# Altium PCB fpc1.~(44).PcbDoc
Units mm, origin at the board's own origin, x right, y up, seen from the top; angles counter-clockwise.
Board outline 89.5 x 7.33 mm, 2 copper layers (Top Layer, Bottom Layer), stack 0.049 mm thick; 5 components, 5 nets, 20 pads, 5 vias.
Unrouted connection lines stored in the file: 8.
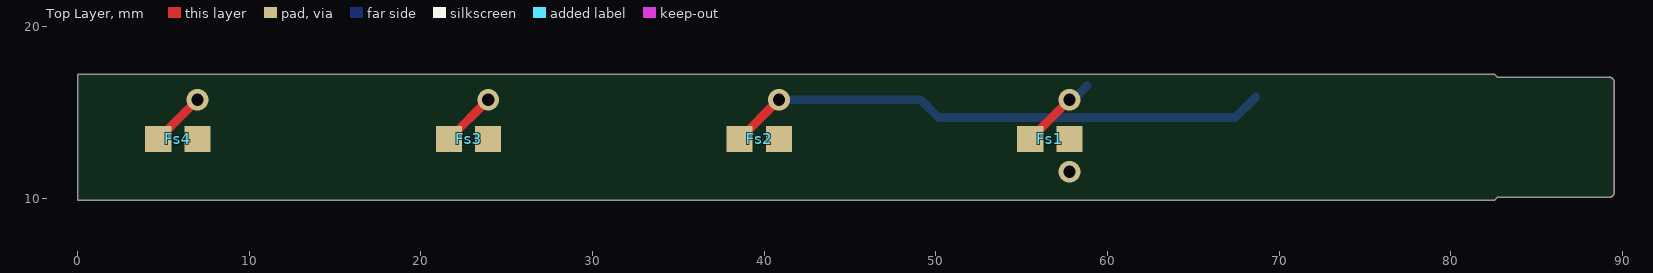
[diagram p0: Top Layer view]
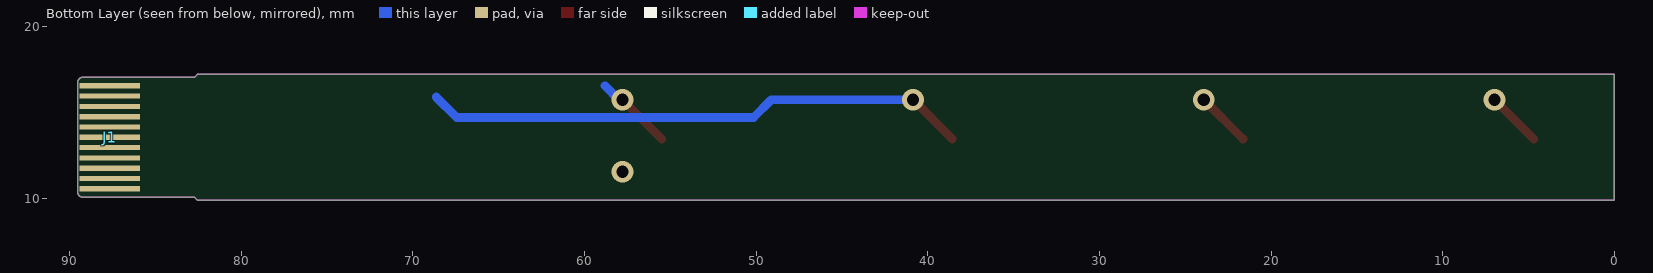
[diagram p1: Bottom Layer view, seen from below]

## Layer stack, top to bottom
Top Solder: solder mask 0.0102, Solder Resist, Dk 3.5
Top Layer: signal copper 0.012
Dielectric 1: dielectric 0.025, FR-4, Dk 4.8
Bottom Layer: signal copper 0.012
Bottom Solder: solder mask 0.0102, Solder Resist, Dk 3.5

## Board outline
0.013,9.893 0.013,17.225 82.547,17.225 82.713,17.059 89.213,17.059 cw(c89.213,16.759) 89.513,16.759 89.513,10.359 cw(c89.213,10.359) 89.213,10.059 82.713,10.059 82.547,9.893

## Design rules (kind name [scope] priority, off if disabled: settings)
BoardOutlineClearance [All] p1: gap=0 ignorepadtopadclearanceinfootprint=FALSE except(0.254: Via-OutlineEdge Via-CavityEdge Via-CutoutEdge Via-SplitBarrior Fill-OutlineEdge Fill-CavityEdge Fill-CutoutEdge Fill-SplitBarrior Poly-OutlineEdge Poly-CavityEdge Poly-CutoutEdge Poly-SplitBarrior Region-OutlineEdge Region-CavityEdge Region-CutoutEdge Region-SplitBarrior Text-OutlineEdge Text-CavityEdge Text-CutoutEdge Text-SplitBarrior)
Clearance [All] p1: gap=0.076 ignorepadtopadclearanceinfootprint=TRUE except(0: Arc-Hole Track-Hole SMDPad-Hole THPad-Hole Via-Hole Fill-Hole Poly-Hole Region-Hole Text-Hole)
DiffPairsRouting [All] p1: maxlimit=0.254 minlimit=0.254 mostfreqgap=0.254 toplayer_minwidth=0.381 toplayer_maxwidth=0.381 toplayer_prefwidth=0.381 bottomlayer_minwidth=0.381 bottomlayer_maxwidth=0.381 bottomlayer_prefwidth=0.381 substack1={6BAC4FC8-8DE6-4E41-AF8A-9441F3E19743} toplayer_{6bac4fc8-8de6-4e41-af8a-9441f3e19743}_minwidth=0.381 toplayer_{6bac4fc8-8de6-4e41-af8a-9441f3e19743}_maxwidth=0.381 toplayer_{6bac4fc8-8de6-4e41-af8a-9441f3e19743}_prefwidth=0.381 bottomlayer_{6bac4fc8-8de6-4e41-af8a-9441f3e19743}_minwidth=0.381 bottomlayer_{6bac4fc8-8de6-4e41-af8a-9441f3e19743}_maxwidth=0.381 bottomlayer_{6bac4fc8-8de6-4e41-af8a-9441f3e19743}_prefwidth=0.381 maxuncoupledlength=12.7
MinimumSolderMaskSliver [All] p1: minsoldermaskwidth=0.05
PolygonConnect [All] p1: connectstyle=Relief reliefconductorwidth=0.254 reliefentries=4 polygonreliefangle="90 Angle" airgapwidth=0.254
RoutingVias [All] p1: holewidth=0.711 width=1.27 viastyle="Through Hole" minholewidth=0.711 minwidth=1.27 maxholewidth=0.711 maxwidth=1.27
SilkToSilkClearance [All] p1: silktosilkclearance=0.05
SilkToSolderMaskClearance [IsPad] p1: minsilkscreentomaskgap=0.05 clearancetoexposedcopper=TRUE
SolderMaskExpansion [All] p1: expansion=0.102 istentingtop=FALSE
Width [All] p1: maxlimit=0.508 minlimit=0.254 preferedwidth=0.381 substack1={6BAC4FC8-8DE6-4E41-AF8A-9441F3E19743} toplayer_{6bac4fc8-8de6-4e41-af8a-9441f3e19743}_maxwidth=0.254 toplayer_{6bac4fc8-8de6-4e41-af8a-9441f3e19743}_prefwidth=0.254 bottomlayer_{6bac4fc8-8de6-4e41-af8a-9441f3e19743}_maxwidth=0.254 bottomlayer_{6bac4fc8-8de6-4e41-af8a-9441f3e19743}_prefwidth=0.254 minimp=50.000000 maximp=50.000000 favimp=50.000000
26 further rules are at their usual default settings.

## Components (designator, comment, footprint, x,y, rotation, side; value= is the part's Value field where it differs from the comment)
Fs1 "ForceSensor" sensor_connector 56.642,13.462 r0 top
Fs2 "ForceSensor" sensor_connector 39.709,13.462 r0 top
Fs3 "ForceSensor" sensor_connector 22.775,13.462 r0 top
Fs4 "ForceSensor" sensor_connector 5.842,13.462 r0 top
J1 "FPC_connector" FPC_connector 87.65,13.559 r180 bottom

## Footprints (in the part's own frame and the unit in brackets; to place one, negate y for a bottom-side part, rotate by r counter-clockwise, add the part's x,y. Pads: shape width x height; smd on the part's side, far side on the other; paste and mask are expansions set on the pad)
FPC_connector [mm]
  rect 3.5x0.3 smd: 0(0,3) 1(0,3) 2(0,2.4) 3(0,1.8) 4(0,1.2) 5(0,0.6) 6(0,0) 7(0,-0.6) 8(0,-1.2) 9(0,-1.8) 10(0,-2.4) 11(0,-3)
sensor_connector [mil]
  rect 60x60 smd: 0(-45,0) 1(45,0)

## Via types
v1: diameter 1.27, hole 0.711, Top Layer to Bottom Layer, 5 vias

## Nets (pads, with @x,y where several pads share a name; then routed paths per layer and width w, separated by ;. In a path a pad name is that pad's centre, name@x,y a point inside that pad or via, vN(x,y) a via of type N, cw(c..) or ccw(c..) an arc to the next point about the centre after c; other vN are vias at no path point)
FS1: Fs1.0 J1.1 | length 4.6
  Top Layer w0.508: Fs1.0 v1(57.785,15.748)
  Bottom Layer w0.508: v1(57.785,15.748) 57.991,15.748 58.802,16.559
FS2: Fs2.0 J1.2 | length 31.9
  Top Layer w0.508: Fs2.0 v1(40.852,15.748)
  Bottom Layer w0.508: v1(40.852,15.748) 49.117,15.748 50.156,14.709 67.433,14.709 68.625,15.901
FS3: Fs3.0 J1.3 | length 3.2
  Top Layer w0.508: Fs3.0 v1(23.918,15.748)
FS4: Fs4.0 J1.4 | length 3.2
  Top Layer w0.508: Fs4.0 v1(6.985,15.748)
GND: Fs1.1 Fs2.1 Fs3.1 Fs4.1 J1.0
pads on no net: J1.5 J1.6 J1.7 J1.8 J1.9 J1.10 J1.11
copper on no net:
  other v1: 57.785,11.557

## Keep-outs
Keep-Out Layer:
  the board outline again, w0.013

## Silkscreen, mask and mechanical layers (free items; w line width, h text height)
Board Shape:
  the board outline again, w0.013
